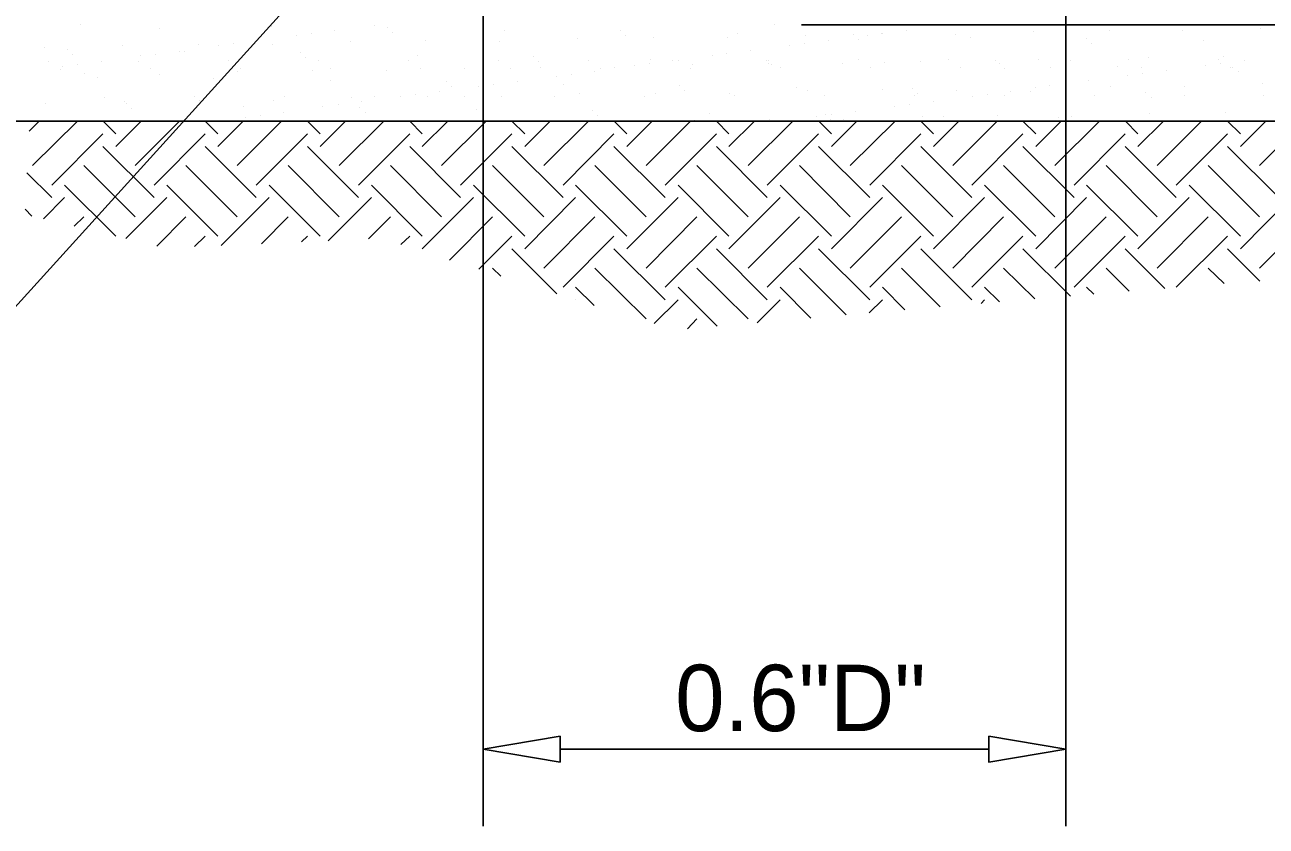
# Model space of a CAD drawing. Extents: x -118779 to -116979, y -104389 to -102939.
# Drawn here: x -117577.5 to -117465.3, y -103405.2 to -103332.8 of the extents above; entities that cross this region are included whole.
import ezdxf

# ---------------------------------------------------------------- set-up
doc = ezdxf.new("R2010")
doc.units = 0
for name, color, linetype in [('G-MARK', 7, 'Continuous'), ('G-TEXT', 7, 'Continuous'), ('Misc CnstDet(22)', 7, 'Continuous')]:
    doc.layers.add(name, color=color, linetype=linetype)

msp = doc.modelspace()

# ---------------------------------------------------------------- linework, layer by layer
at = {"layer": 'G-MARK'}
for p, q in [((-117536.07, -103314.91), (-117536.07, -103405.2)), ((-117483.42, -103314.91), (-117483.42, -103405.2)), ((-117507.31, -103332.8), (-117367.22, -103332.8)), ((-117507.31, -103341.51), (-117367.22, -103341.51)), ((-117529.11, -103398.24), (-117490.38, -103398.24))]:
    msp.add_line(p, q, dxfattribs=at)
msp.add_lwpolyline([(-117533.5, -103308.81), (-117592.7, -103374.11), (-117604.01, -103374.11)], dxfattribs=at)
at = {"layer": 'G-TEXT'}
for points in [[(-117529.11, -103397.07), (-117529.11, -103399.4), (-117536.07, -103398.24)], [(-117490.38, -103397.07), (-117490.38, -103399.4), (-117483.42, -103398.24)]]:
    msp.add_lwpolyline(points, close=True, dxfattribs=at)
at = {"layer": 'Misc CnstDet(22)'}
for p, q in [((-117572.41, -103332.8), (-117572.41, -103332.8)), ((-117565.31, -103333.14), (-117565.31, -103333.14)), ((-117555.16, -103332.94), (-117555.16, -103332.94)), ((-117549.47, -103333.32), (-117549.47, -103333.32)), ((-117545.91, -103332.84), (-117545.91, -103332.84)), ((-117544.71, -103333.04), (-117544.71, -103333.04)), ((-117544.23, -103333.49), (-117544.23, -103333.49)), ((-117534.12, -103333.28), (-117534.12, -103333.28)), ((-117523.66, -103333.35), (-117523.66, -103333.35)), ((-117509.75, -103332.8), (-117509.75, -103332.8)), ((-117497.85, -103333.28), (-117497.85, -103333.28)), ((-117494.29, -103332.8), (-117494.29, -103332.8)), ((-117486.37, -103333.42), (-117486.37, -103333.42)), ((-117479.51, -103333.32), (-117479.51, -103333.32)), ((-117472.86, -103333.35), (-117472.86, -103333.35)), ((-117465.8, -103333.11), (-117465.8, -103333.11)), ((-117561.81, -103334.55), (-117561.81, -103334.55)), ((-117558.63, -103334.52), (-117558.63, -103334.52)), ((-117556.5, -103334.24), (-117556.5, -103334.24)), ((-117555.13, -103334.58), (-117555.13, -103334.58)), ((-117552.94, -103333.76), (-117552.94, -103333.76)), ((-117551.6, -103333.59), (-117551.6, -103333.59)), ((-117548.07, -103334.34), (-117548.07, -103334.34)), ((-117541.25, -103334.24), (-117541.25, -103334.24)), ((-117534.56, -103334.28), (-117534.56, -103334.28)), ((-117527.5, -103334.04), (-117527.5, -103334.04)), ((-117523.18, -103333.8), (-117523.18, -103333.8)), ((-117520.68, -103333.93), (-117520.68, -103333.93)), ((-117514, -103333.97), (-117514, -103333.97)), ((-117513.07, -103333.59), (-117513.07, -103333.59)), ((-117507, -103334.48), (-117507, -103334.48)), ((-117506.94, -103333.73), (-117506.94, -103333.73)), ((-117504.88, -103334.21), (-117504.88, -103334.21)), ((-117502.62, -103333.69), (-117502.62, -103333.69)), ((-117502.14, -103334.14), (-117502.14, -103334.14)), ((-117501.31, -103333.73), (-117501.31, -103333.73)), ((-117500.11, -103333.62), (-117500.11, -103333.62)), ((-117499.98, -103333.56), (-117499.98, -103333.56)), ((-117493.43, -103333.66), (-117493.43, -103333.66)), ((-117491.99, -103333.9), (-117491.99, -103333.9)), ((-117481.57, -103334), (-117481.57, -103334)), ((-117481.06, -103334.45), (-117481.06, -103334.45)), ((-117470.94, -103334.24), (-117470.94, -103334.24)), ((-117575.7, -103334.89), (-117575.7, -103334.89)), ((-117573.64, -103335), (-117573.64, -103335)), ((-117573.16, -103335.44), (-117573.16, -103335.44)), ((-117568.67, -103334.65), (-117568.67, -103334.65)), ((-117566.99, -103335.61), (-117566.99, -103335.61)), ((-117565.65, -103335.44), (-117565.65, -103335.44)), ((-117563.53, -103335.17), (-117563.53, -103335.17)), ((-117563.01, -103335.24), (-117563.01, -103335.24)), ((-117559.96, -103334.69), (-117559.96, -103334.69)), ((-117552.59, -103335.34), (-117552.59, -103335.34)), ((-117541.97, -103335.58), (-117541.97, -103335.58)), ((-117531.51, -103335.65), (-117531.51, -103335.65)), ((-117515.37, -103335.58), (-117515.37, -103335.58)), ((-117514.03, -103335.41), (-117514.03, -103335.41)), ((-117511.91, -103335.13), (-117511.91, -103335.13)), ((-117508.34, -103334.65), (-117508.34, -103334.65)), ((-117469.16, -103335.68), (-117469.16, -103335.68)), ((-117575.35, -103336.09), (-117575.35, -103336.09)), ((-117574.26, -103336.81), (-117574.26, -103336.81)), ((-117574.05, -103336.54), (-117574.05, -103336.54)), ((-117572.68, -103336.37), (-117572.68, -103336.37)), ((-117570.55, -103336.09), (-117570.55, -103336.09)), ((-117567.23, -103336.09), (-117567.23, -103336.09)), ((-117566.13, -103336.78), (-117566.13, -103336.78)), ((-117559.07, -103336.06), (-117559.07, -103336.06)), ((-117557.97, -103336.78), (-117557.97, -103336.78)), ((-117552.08, -103335.78), (-117552.08, -103335.78)), ((-117550.95, -103336.06), (-117550.95, -103336.06)), ((-117549.85, -103336.78), (-117549.85, -103336.78)), ((-117542.82, -103336.06), (-117542.82, -103336.06)), ((-117541.73, -103336.74), (-117541.73, -103336.74)), ((-117537.72, -103336.71), (-117537.72, -103336.71)), ((-117534.67, -103336.02), (-117534.67, -103336.02)), ((-117533.57, -103336.74), (-117533.57, -103336.74)), ((-117531.03, -103336.09), (-117531.03, -103336.09)), ((-117530.9, -103336.61), (-117530.9, -103336.61)), ((-117526.54, -103336.02), (-117526.54, -103336.02)), ((-117525.45, -103336.71), (-117525.45, -103336.71)), ((-117524.21, -103336.64), (-117524.21, -103336.64)), ((-117522.43, -103336.5), (-117522.43, -103336.5)), ((-117521.06, -103336.33), (-117521.06, -103336.33)), ((-117520.92, -103335.89), (-117520.92, -103335.89)), ((-117518.93, -103336.06), (-117518.93, -103336.06)), ((-117518.42, -103335.99), (-117518.42, -103335.99)), ((-117517.32, -103336.71), (-117517.32, -103336.71)), ((-117517.15, -103336.4), (-117517.15, -103336.4)), ((-117510.47, -103335.99), (-117510.47, -103335.99)), ((-117510.29, -103335.99), (-117510.29, -103335.99)), ((-117510.29, -103336.3), (-117510.29, -103336.3)), ((-117509.99, -103336.4), (-117509.99, -103336.4)), ((-117509.16, -103336.67), (-117509.16, -103336.67)), ((-117503.61, -103336.33), (-117503.61, -103336.33)), ((-117502.14, -103335.96), (-117502.14, -103335.96)), ((-117501.04, -103336.67), (-117501.04, -103336.67)), ((-117499.84, -103336.2), (-117499.84, -103336.2)), ((-117496.58, -103336.09), (-117496.58, -103336.09)), ((-117494.01, -103335.96), (-117494.01, -103335.96)), ((-117492.92, -103336.64), (-117492.92, -103336.64)), ((-117489.73, -103335.99), (-117489.73, -103335.99)), ((-117489.42, -103336.3), (-117489.42, -103336.3)), ((-117488.94, -103336.74), (-117488.94, -103336.74)), ((-117485.89, -103335.96), (-117485.89, -103335.96)), ((-117484.79, -103336.64), (-117484.79, -103336.64)), ((-117483.04, -103336.02), (-117483.04, -103336.02)), ((-117478.79, -103336.54), (-117478.79, -103336.54)), ((-117477.73, -103335.92), (-117477.73, -103335.92)), ((-117476.63, -103336.64), (-117476.63, -103336.64)), ((-117475.98, -103335.78), (-117475.98, -103335.78)), ((-117470.77, -103336.47), (-117470.77, -103336.47)), ((-117469.61, -103335.92), (-117469.61, -103335.92)), ((-117469.44, -103336.3), (-117469.44, -103336.3)), ((-117468.51, -103336.61), (-117468.51, -103336.61)), ((-117468.34, -103336.61), (-117468.34, -103336.61)), ((-117467.31, -103336.02), (-117467.31, -103336.02)), ((-117572.03, -103337.22), (-117572.03, -103337.22)), ((-117570.86, -103337.53), (-117570.86, -103337.53)), ((-117565.34, -103337.26), (-117565.34, -103337.26)), ((-117560.44, -103337.63), (-117560.44, -103337.63)), ((-117558.28, -103337.02), (-117558.28, -103337.02)), ((-117551.46, -103336.91), (-117551.46, -103336.91)), ((-117549.82, -103337.84), (-117549.82, -103337.84)), ((-117544.78, -103336.95), (-117544.78, -103336.95)), ((-117539.36, -103337.94), (-117539.36, -103337.94)), ((-117532.99, -103337.91), (-117532.99, -103337.91)), ((-117529.46, -103337.43), (-117529.46, -103337.43)), ((-117528.08, -103337.26), (-117528.08, -103337.26)), ((-117525.96, -103336.98), (-117525.96, -103336.98)), ((-117481.36, -103337.87), (-117481.36, -103337.87)), ((-117477.83, -103337.39), (-117477.83, -103337.39)), ((-117476.46, -103337.22), (-117476.46, -103337.22)), ((-117474.34, -103336.95), (-117474.34, -103336.95)), ((-117467.86, -103337.05), (-117467.86, -103337.05)), ((-117559.96, -103338.08), (-117559.96, -103338.08)), ((-117540.01, -103338.83), (-117540.01, -103338.83)), ((-117538.88, -103338.39), (-117538.88, -103338.39)), ((-117536.48, -103338.35), (-117536.48, -103338.35)), ((-117535.11, -103338.18), (-117535.11, -103338.18)), ((-117528.77, -103338.18), (-117528.77, -103338.18)), ((-117527.33, -103339.04), (-117527.33, -103339.04)), ((-117520.51, -103338.97), (-117520.51, -103338.97)), ((-117518.32, -103338.25), (-117518.32, -103338.25)), ((-117517.84, -103338.7), (-117517.84, -103338.7)), ((-117513.83, -103339.01), (-117513.83, -103339.01)), ((-117507.72, -103338.49), (-117507.72, -103338.49)), ((-117506.76, -103338.73), (-117506.76, -103338.73)), ((-117499.94, -103338.66), (-117499.94, -103338.66)), ((-117497.27, -103338.59), (-117497.27, -103338.59)), ((-117496.79, -103339.04), (-117496.79, -103339.04)), ((-117493.26, -103338.7), (-117493.26, -103338.7)), ((-117490.52, -103339.07), (-117490.52, -103339.07)), ((-117488.39, -103338.8), (-117488.39, -103338.8)), ((-117486.64, -103338.83), (-117486.64, -103338.83)), ((-117486.2, -103338.42), (-117486.2, -103338.42)), ((-117484.86, -103338.32), (-117484.86, -103338.32)), ((-117483.49, -103338.15), (-117483.49, -103338.15)), ((-117479.38, -103338.35), (-117479.38, -103338.35)), ((-117476.19, -103338.9), (-117476.19, -103338.9)), ((-117472.69, -103338.39), (-117472.69, -103338.39)), ((-117465.63, -103338.11), (-117465.63, -103338.11)), ((-117575.56, -103339.93), (-117575.56, -103339.93)), ((-117570.28, -103339.35), (-117570.28, -103339.35)), ((-117568.5, -103339.69), (-117568.5, -103339.69)), ((-117568.29, -103339.93), (-117568.29, -103339.93)), ((-117562.16, -103339.31), (-117562.16, -103339.31)), ((-117561.64, -103339.59), (-117561.64, -103339.59)), ((-117557.67, -103340.14), (-117557.67, -103340.14)), ((-117554.96, -103339.62), (-117554.96, -103339.62)), ((-117554.03, -103339.31), (-117554.03, -103339.31)), ((-117550.54, -103340.21), (-117550.54, -103340.21)), ((-117549.17, -103340.03), (-117549.17, -103340.03)), ((-117547.93, -103339.38), (-117547.93, -103339.38)), ((-117547.04, -103339.76), (-117547.04, -103339.76)), ((-117545.87, -103339.28), (-117545.87, -103339.28)), ((-117543.51, -103339.28), (-117543.51, -103339.28)), ((-117542.14, -103339.11), (-117542.14, -103339.11)), ((-117541.08, -103339.28), (-117541.08, -103339.28)), ((-117537.75, -103339.28), (-117537.75, -103339.28)), ((-117534.39, -103339.31), (-117534.39, -103339.31)), ((-117529.63, -103339.25), (-117529.63, -103339.25)), ((-117521.47, -103339.25), (-117521.47, -103339.25)), ((-117513.35, -103339.21), (-117513.35, -103339.21)), ((-117505.22, -103339.21), (-117505.22, -103339.21)), ((-117498.91, -103340.17), (-117498.91, -103340.17)), ((-117497.54, -103340), (-117497.54, -103340)), ((-117497.06, -103339.21), (-117497.06, -103339.21)), ((-117495.42, -103339.73), (-117495.42, -103339.73)), ((-117491.89, -103339.25), (-117491.89, -103339.25)), ((-117488.94, -103339.18), (-117488.94, -103339.18)), ((-117480.82, -103339.18), (-117480.82, -103339.18)), ((-117475.71, -103339.35), (-117475.71, -103339.35)), ((-117472.69, -103339.14), (-117472.69, -103339.14)), ((-117465.6, -103339.14), (-117465.6, -103339.14)), ((-117567.81, -103340.34), (-117567.81, -103340.34)), ((-117557.56, -103341.13), (-117557.56, -103341.13)), ((-117556.19, -103340.96), (-117556.19, -103340.96)), ((-117554.07, -103340.69), (-117554.07, -103340.69)), ((-117547.21, -103340.24), (-117547.21, -103340.24)), ((-117546.73, -103340.69), (-117546.73, -103340.69)), ((-117536.62, -103340.48), (-117536.62, -103340.48)), ((-117526.16, -103340.55), (-117526.16, -103340.55)), ((-117525.69, -103340.99), (-117525.69, -103340.99)), ((-117515.57, -103340.79), (-117515.57, -103340.79)), ((-117510.16, -103341.34), (-117510.16, -103341.34)), ((-117505.94, -103341.1), (-117505.94, -103341.1)), ((-117505.12, -103340.89), (-117505.12, -103340.89)), ((-117504.64, -103341.34), (-117504.64, -103341.34)), ((-117504.57, -103340.93), (-117504.57, -103340.93)), ((-117502.44, -103340.65), (-117502.44, -103340.65)), ((-117496.41, -103341.1), (-117496.41, -103341.1)), ((-117494.49, -103341.1), (-117494.49, -103341.1)), ((-117489.56, -103341.03), (-117489.56, -103341.03)), ((-117484.04, -103341.2), (-117484.04, -103341.2)), ((-117482.87, -103341.06), (-117482.87, -103341.06)), ((-117475.85, -103340.79), (-117475.85, -103340.79)), ((-117468.99, -103340.72), (-117468.99, -103340.72)), ((-117597.5, -103341.51), (-117422.06, -103341.51)), ((-117577.07, -103342.4), (-117576.18, -103341.51)), ((-117576.76, -103345.52), (-117572.71, -103341.51)), ((-117569.25, -103342.64), (-117570.38, -103341.51)), ((-117569.25, -103343.8), (-117566.96, -103341.51)), ((-117567.5, -103345.52), (-117563.49, -103341.51)), ((-117560.03, -103342.64), (-117561.16, -103341.51)), ((-117560.03, -103343.8), (-117557.73, -103341.51)), ((-117558.28, -103345.52), (-117554.27, -103341.51)), ((-117550.78, -103342.64), (-117551.94, -103341.51)), ((-117550.78, -103343.8), (-117548.48, -103341.51)), ((-117549.06, -103345.52), (-117545.02, -103341.51)), ((-117541.56, -103342.64), (-117542.69, -103341.51)), ((-117541.56, -103343.8), (-117539.26, -103341.51)), ((-117539.81, -103345.52), (-117535.8, -103341.51)), ((-117532.3, -103342.64), (-117533.47, -103341.51)), ((-117532.3, -103343.8), (-117530, -103341.51)), ((-117530.59, -103345.52), (-117526.54, -103341.51)), ((-117523.08, -103342.64), (-117524.21, -103341.51)), ((-117523.08, -103343.8), (-117520.78, -103341.51)), ((-117521.33, -103345.52), (-117517.32, -103341.51)), ((-117516.98, -103341.41), (-117516.98, -103341.41)), ((-117513.86, -103342.64), (-117514.99, -103341.51)), ((-117513.86, -103343.8), (-117511.56, -103341.51)), ((-117512.11, -103345.52), (-117508.07, -103341.51)), ((-117509.75, -103341.51), (-117509.75, -103341.51)), ((-117504.6, -103342.64), (-117505.74, -103341.51)), ((-117504.6, -103343.8), (-117502.31, -103341.51)), ((-117503.47, -103341.37), (-117503.47, -103341.37)), ((-117502.89, -103345.52), (-117498.85, -103341.51)), ((-117495.38, -103342.64), (-117496.51, -103341.51)), ((-117495.38, -103343.8), (-117493.09, -103341.51)), ((-117493.64, -103345.52), (-117489.63, -103341.51)), ((-117486.13, -103342.64), (-117487.29, -103341.51)), ((-117486.13, -103343.8), (-117483.83, -103341.51)), ((-117484.42, -103345.52), (-117480.37, -103341.51)), ((-117476.91, -103342.64), (-117478.04, -103341.51)), ((-117476.91, -103343.8), (-117474.61, -103341.51)), ((-117475.16, -103345.52), (-117471.15, -103341.51)), ((-117473.45, -103341.44), (-117473.45, -103341.44)), ((-117467.65, -103342.64), (-117468.82, -103341.51)), ((-117467.65, -103343.8), (-117465.36, -103341.51)), ((-117465.94, -103345.52), (-117461.89, -103341.51)), ((-117575.01, -103347.27), (-117570.42, -103342.64)), ((-117565.79, -103347.27), (-117561.16, -103342.64)), ((-117556.57, -103347.27), (-117551.94, -103342.64)), ((-117547.31, -103347.27), (-117542.69, -103342.64)), ((-117538.09, -103347.27), (-117533.47, -103342.64)), ((-117528.84, -103347.27), (-117524.25, -103342.64)), ((-117519.62, -103347.27), (-117514.99, -103342.64)), ((-117510.4, -103347.27), (-117505.77, -103342.64)), ((-117501.14, -103347.27), (-117496.51, -103342.64)), ((-117491.92, -103347.27), (-117487.29, -103342.64)), ((-117482.67, -103347.27), (-117478.07, -103342.64)), ((-117473.45, -103347.27), (-117468.82, -103342.64)), ((-117565.79, -103348.4), (-117570.42, -103343.8)), ((-117556.57, -103348.4), (-117561.16, -103343.8)), ((-117547.31, -103348.4), (-117551.94, -103343.8)), ((-117538.09, -103348.4), (-117542.69, -103343.8)), ((-117528.84, -103348.4), (-117533.47, -103343.8)), ((-117519.62, -103348.4), (-117524.25, -103343.8)), ((-117510.4, -103348.4), (-117514.99, -103343.8)), ((-117501.14, -103348.4), (-117505.77, -103343.8)), ((-117491.92, -103348.4), (-117496.51, -103343.8)), ((-117482.67, -103348.4), (-117487.29, -103343.8)), ((-117473.45, -103348.4), (-117478.07, -103343.8)), ((-117464.19, -103348.4), (-117468.82, -103343.8)), ((-117567.5, -103350.15), (-117572.13, -103345.52)), ((-117558.28, -103350.15), (-117562.91, -103345.52)), ((-117549.06, -103350.15), (-117553.66, -103345.52)), ((-117539.81, -103350.15), (-117544.43, -103345.52)), ((-117530.59, -103350.15), (-117535.21, -103345.52)), ((-117521.33, -103350.15), (-117525.96, -103345.52)), ((-117512.11, -103350.15), (-117516.74, -103345.52)), ((-117502.89, -103350.15), (-117507.48, -103345.52)), ((-117493.64, -103350.15), (-117498.26, -103345.52)), ((-117484.42, -103350.15), (-117489.04, -103345.52)), ((-117475.16, -103350.15), (-117479.79, -103345.52)), ((-117465.94, -103350.15), (-117470.57, -103345.52)), ((-117575.01, -103348.4), (-117577.27, -103346.17)), ((-117569.25, -103351.89), (-117573.88, -103347.27)), ((-117560.03, -103351.89), (-117564.62, -103347.27)), ((-117550.78, -103351.89), (-117555.4, -103347.27)), ((-117541.56, -103351.89), (-117546.15, -103347.27)), ((-117532.3, -103351.89), (-117536.93, -103347.27)), ((-117523.08, -103351.89), (-117527.71, -103347.27)), ((-117513.86, -103351.89), (-117518.45, -103347.27)), ((-117504.6, -103351.89), (-117509.23, -103347.27)), ((-117495.38, -103351.89), (-117499.98, -103347.27)), ((-117486.13, -103351.89), (-117490.76, -103347.27)), ((-117476.91, -103351.89), (-117481.54, -103347.27)), ((-117467.65, -103351.89), (-117472.28, -103347.27)), ((-117575.76, -103350.32), (-117573.88, -103348.4)), ((-117568.33, -103352.1), (-117564.62, -103348.4)), ((-117559.72, -103352.72), (-117555.4, -103348.4)), ((-117550.06, -103352.31), (-117546.15, -103348.4)), ((-117541.56, -103353.03), (-117536.93, -103348.4)), ((-117532.3, -103353.03), (-117527.71, -103348.4)), ((-117523.08, -103353.03), (-117518.45, -103348.4)), ((-117513.86, -103353.03), (-117509.23, -103348.4)), ((-117504.6, -103353.03), (-117499.98, -103348.4)), ((-117495.38, -103353.03), (-117490.76, -103348.4)), ((-117486.13, -103353.03), (-117481.54, -103348.4)), ((-117476.91, -103353.03), (-117472.28, -103348.4)), ((-117467.65, -103353.03), (-117463.06, -103348.4)), ((-117576.83, -103350.08), (-117577.44, -103349.46)), ((-117572.99, -103351), (-117572.13, -103350.15)), ((-117565.55, -103352.79), (-117562.91, -103350.15)), ((-117556.09, -103352.58), (-117553.66, -103350.15)), ((-117546.42, -103352.13), (-117544.43, -103350.15)), ((-117539.09, -103354.05), (-117535.21, -103350.15)), ((-117530.59, -103354.77), (-117525.96, -103350.15)), ((-117521.33, -103354.77), (-117516.74, -103350.15)), ((-117512.11, -103354.77), (-117507.48, -103350.15)), ((-117502.89, -103354.77), (-117498.26, -103350.15)), ((-117493.64, -103354.77), (-117489.04, -103350.15)), ((-117484.42, -103354.77), (-117479.79, -103350.15)), ((-117475.16, -103354.77), (-117470.57, -103350.15)), ((-117465.94, -103354.77), (-117461.31, -103350.15)), ((-117562.12, -103352.82), (-117561.16, -103351.89)), ((-117552.46, -103352.41), (-117551.94, -103351.89)), ((-117543.48, -103352.65), (-117542.69, -103351.89)), ((-117536.45, -103354.88), (-117533.47, -103351.89)), ((-117528.84, -103356.49), (-117524.25, -103351.89)), ((-117519.62, -103356.49), (-117514.99, -103351.89)), ((-117510.4, -103356.49), (-117505.77, -103351.89)), ((-117501.14, -103356.49), (-117496.51, -103351.89)), ((-117491.92, -103356.49), (-117487.29, -103351.89)), ((-117482.67, -103356.49), (-117478.07, -103351.89)), ((-117473.45, -103356.49), (-117468.82, -103351.89)), ((-117529.39, -103357.1), (-117533.47, -103353.03)), ((-117519.62, -103357.65), (-117524.25, -103353.03)), ((-117510.4, -103357.65), (-117514.99, -103353.03)), ((-117501.14, -103357.65), (-117505.77, -103353.03)), ((-117491.92, -103357.65), (-117496.51, -103353.03)), ((-117483.01, -103357.31), (-117487.29, -103353.03)), ((-117474.47, -103356.62), (-117478.07, -103353.03)), ((-117465.91, -103355.97), (-117468.82, -103353.03)), ((-117534.46, -103355.49), (-117535.21, -103354.77)), ((-117521.33, -103359.37), (-117525.96, -103354.77)), ((-117512.11, -103359.37), (-117516.74, -103354.77)), ((-117503.27, -103358.99), (-117507.48, -103354.77)), ((-117494.77, -103358.27), (-117498.26, -103354.77)), ((-117486.23, -103357.55), (-117489.04, -103354.77)), ((-117477.7, -103356.86), (-117479.79, -103354.77)), ((-117469.13, -103356.18), (-117470.57, -103354.77)), ((-117526.03, -103358.17), (-117527.71, -103356.49)), ((-117514.92, -103360.02), (-117518.45, -103356.49)), ((-117506.46, -103359.3), (-117509.23, -103356.49)), ((-117497.95, -103358.54), (-117499.98, -103356.49)), ((-117489.42, -103357.82), (-117490.76, -103356.49)), ((-117480.88, -103357.14), (-117481.54, -103356.49)), ((-117527.71, -103357.65), (-117527.71, -103357.65)), ((-117520.61, -103359.78), (-117518.45, -103357.65)), ((-117511.29, -103359.71), (-117509.23, -103357.65)), ((-117501.18, -103358.82), (-117499.98, -103357.65)), ((-117491.06, -103357.96), (-117490.76, -103357.65)), ((-117517.6, -103360.26), (-117516.74, -103359.37)), ((-117483.42, -103398.24), (-117483.42, -103398.24))]:
    msp.add_line(p, q, dxfattribs=at)

# ---------------------------------------------------------------- texts
msp.add_text('0.6"D"', height=6, dxfattribs=at).set_placement((-117518.71, -103396.61))

doc.saveas('drawing.dxf')
